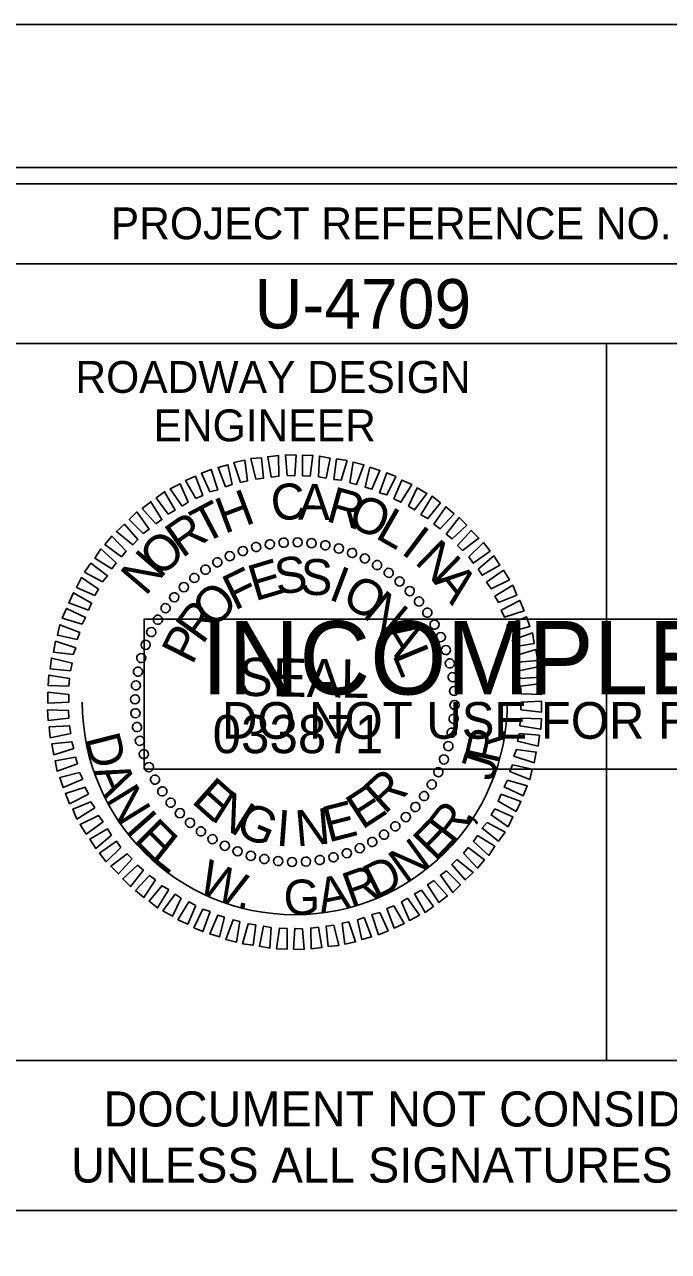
# Model space of a CAD drawing. Extents: x 1779926 to 1781626, y 618464 to 619564.
# Drawn here: x 1781401.6 to 1781502.7, y 619371.7 to 619564.2 of the extents above; entities that cross this region are included whole.
import ezdxf

# ---------------------------------------------------------------- set-up
doc = ezdxf.new("R2010")
doc.units = 0
for name, color, linetype in [('Old_Level_58', 7, 'Continuous'), ('Scratch_Level_0', 7, 'Continuous'), ('Sheet Data Field CELL', 7, 'Continuous'), ('Sheet Plot Border Inside CELL', 7, 'Continuous'), ('Sheet Plot Border Outside CELL', 7, 'Continuous'), ('Sheet Professional Seal CELL', 7, 'Continuous'), ('Sheet Profile CELL', 7, 'Continuous'), ('Sheet Profile Grid Major CELL', 7, 'Continuous'), ('Sheet Profile Grid Minor CELL', 7, 'Continuous'), ('Sheet Sticker Exception Certification CELL', 7, 'Continuous'), ('Sheet Sticker Incomplete CELL', 7, 'Continuous')]:
    doc.layers.add(name, color=color, linetype=linetype)

msp = doc.modelspace()

# ---------------------------------------------------------------- linework, layer by layer
at = {"layer": 'Old_Level_58'}
msp.add_lwpolyline([(1781392.96, 619378.14), (1781592.95, 619378.14), (1781592.95, 619314.19), (1781392.96, 619314.19)], close=True, dxfattribs=at)
at = {"layer": 'Scratch_Level_0'}
msp.add_arc((1781444.02, 619457.88), 33.36, 180, 360, dxfattribs=at)
at = {"layer": 'Sheet Plot Border Inside CELL'}
msp.add_lwpolyline([(1779938.96, 618486.64), (1781605.46, 618486.64), (1781605.46, 619541.74), (1779938.96, 619541.74)], close=True, dxfattribs=at)
at = {"layer": 'Sheet Plot Border Outside CELL'}
msp.add_lwpolyline([(1779925.96, 618464.19), (1781625.96, 618464.19), (1781625.96, 619564.19), (1779925.96, 619564.19)], close=True, dxfattribs=at)
at = {"layer": 'Sheet Professional Seal CELL'}
for p, q in [((1781440.12, 619482.63), (1781440.12, 619482.63)), ((1781442.27, 619482.93), (1781442.27, 619482.93)), ((1781444.47, 619482.98), (1781444.47, 619482.98)), ((1781446.67, 619482.83), (1781446.67, 619482.83)), ((1781448.82, 619482.48), (1781448.82, 619482.48)), ((1781433.82, 619480.83), (1781433.82, 619480.83)), ((1781435.82, 619481.63), (1781435.82, 619481.63)), ((1781437.92, 619482.23), (1781437.92, 619482.23)), ((1781450.92, 619482.03), (1781450.92, 619482.03)), ((1781453.02, 619481.33), (1781453.02, 619481.33)), ((1781455.02, 619480.43), (1781455.02, 619480.43)), ((1781429.97, 619478.68), (1781429.97, 619478.68)), ((1781431.87, 619479.83), (1781431.87, 619479.83)), ((1781456.97, 619479.43), (1781456.97, 619479.43)), ((1781428.22, 619477.43), (1781428.22, 619477.43)), ((1781458.77, 619478.18), (1781458.77, 619478.18)), ((1781460.52, 619476.83), (1781460.52, 619476.83)), ((1781426.57, 619475.93), (1781426.57, 619475.93)), ((1781462.07, 619475.33), (1781462.07, 619475.33)), ((1781425.07, 619474.38), (1781425.07, 619474.38)), ((1781463.57, 619473.68), (1781463.57, 619473.68)), ((1781422.47, 619470.83), (1781422.47, 619470.83)), ((1781423.72, 619472.63), (1781423.72, 619472.63)), ((1781464.82, 619471.93), (1781464.82, 619471.93)), ((1781421.47, 619468.88), (1781421.47, 619468.88)), ((1781465.97, 619470.03), (1781465.97, 619470.03)), ((1781466.97, 619468.08), (1781466.97, 619468.08)), ((1781420.57, 619466.88), (1781420.57, 619466.88)), ((1781467.77, 619466.08), (1781467.77, 619466.08)), ((1781419.87, 619464.78), (1781419.87, 619464.78)), ((1781468.37, 619463.98), (1781468.37, 619463.98)), ((1781419.42, 619462.68), (1781419.42, 619462.68)), ((1781468.77, 619461.78), (1781468.77, 619461.78)), ((1781419.07, 619460.53), (1781419.07, 619460.53)), ((1781469.07, 619459.63), (1781469.07, 619459.63)), ((1781418.92, 619458.33), (1781418.92, 619458.33)), ((1781444.02, 619457.88), (1781444.02, 619457.88)), ((1781469.12, 619457.43), (1781469.12, 619457.43)), ((1781418.97, 619456.13), (1781418.97, 619456.13)), ((1781419.27, 619453.98), (1781419.27, 619453.98)), ((1781468.97, 619455.23), (1781468.97, 619455.23)), ((1781419.67, 619451.78), (1781419.67, 619451.78)), ((1781468.62, 619453.08), (1781468.62, 619453.08)), ((1781420.27, 619449.68), (1781420.27, 619449.68)), ((1781468.17, 619450.98), (1781468.17, 619450.98)), ((1781421.07, 619447.68), (1781421.07, 619447.68)), ((1781467.47, 619448.88), (1781467.47, 619448.88)), ((1781466.57, 619446.88), (1781466.57, 619446.88)), ((1781422.07, 619445.73), (1781422.07, 619445.73)), ((1781423.22, 619443.83), (1781423.22, 619443.83)), ((1781465.57, 619444.93), (1781465.57, 619444.93)), ((1781424.47, 619442.08), (1781424.47, 619442.08)), ((1781464.32, 619443.13), (1781464.32, 619443.13)), ((1781425.97, 619440.43), (1781425.97, 619440.43)), ((1781462.97, 619441.38), (1781462.97, 619441.38)), ((1781427.52, 619438.93), (1781427.52, 619438.93)), ((1781459.82, 619438.33), (1781459.82, 619438.33)), ((1781461.47, 619439.83), (1781461.47, 619439.83)), ((1781429.27, 619437.58), (1781429.27, 619437.58)), ((1781431.07, 619436.33), (1781431.07, 619436.33)), ((1781458.07, 619437.08), (1781458.07, 619437.08)), ((1781433.02, 619435.33), (1781433.02, 619435.33)), ((1781435.02, 619434.43), (1781435.02, 619434.43)), ((1781454.22, 619434.93), (1781454.22, 619434.93)), ((1781456.17, 619435.93), (1781456.17, 619435.93)), ((1781437.12, 619433.73), (1781437.12, 619433.73)), ((1781439.22, 619433.28), (1781439.22, 619433.28)), ((1781441.37, 619432.93), (1781441.37, 619432.93)), ((1781443.57, 619432.78), (1781443.57, 619432.78)), ((1781445.77, 619432.83), (1781445.77, 619432.83)), ((1781447.92, 619433.13), (1781447.92, 619433.13)), ((1781450.12, 619433.53), (1781450.12, 619433.53)), ((1781452.22, 619434.13), (1781452.22, 619434.13))]:
    msp.add_line(p, q, dxfattribs=at)
for points in [[(1781435.52, 619492.33), (1781434.47, 619495.48), (1781436.17, 619495.83), (1781436.57, 619492.58)], [(1781437.92, 619492.88), (1781437.12, 619496.08), (1781438.77, 619496.23), (1781439.12, 619493.03)], [(1781440.32, 619493.18), (1781439.77, 619496.38), (1781441.47, 619496.58), (1781441.52, 619493.33)], [(1781442.82, 619493.43), (1781442.57, 619496.68), (1781444.22, 619496.63), (1781444.02, 619493.38)], [(1781445.22, 619493.38), (1781445.22, 619496.63), (1781446.87, 619496.58), (1781446.42, 619493.33)], [(1781447.72, 619493.23), (1781447.92, 619496.48), (1781449.57, 619496.18), (1781448.92, 619493.03)], [(1781450.12, 619492.83), (1781450.57, 619496.03), (1781452.22, 619495.78), (1781451.32, 619492.68)], [(1781430.67, 619490.88), (1781429.37, 619493.78), (1781430.87, 619494.38), (1781431.92, 619491.18)], [(1781433.12, 619491.68), (1781431.97, 619494.68), (1781433.52, 619495.13), (1781434.17, 619492.03)], [(1781452.67, 619492.28), (1781453.17, 619495.53), (1781454.87, 619495.13), (1781453.72, 619492.03)], [(1781455.07, 619491.63), (1781455.82, 619494.73), (1781457.37, 619494.23), (1781456.12, 619491.28)], [(1781457.32, 619490.73), (1781458.47, 619493.88), (1781459.87, 619493.28), (1781458.47, 619490.38)], [(1781426.32, 619488.63), (1781424.47, 619491.33), (1781426.02, 619492.13), (1781427.27, 619489.23)], [(1781428.47, 619489.83), (1781426.87, 619492.63), (1781428.42, 619493.33), (1781429.57, 619490.28)], [(1781459.57, 619489.78), (1781460.82, 619492.73), (1781462.37, 619492.03), (1781460.67, 619489.23)], [(1781424.12, 619487.38), (1781422.27, 619489.93), (1781423.57, 619490.88), (1781425.22, 619487.98)], [(1781461.87, 619488.63), (1781463.22, 619491.48), (1781464.72, 619490.63), (1781462.82, 619488.03)], [(1781463.82, 619487.28), (1781465.57, 619490.18), (1781466.87, 619489.13), (1781464.92, 619486.68)], [(1781422.22, 619485.88), (1781420.07, 619488.28), (1781421.42, 619489.33), (1781423.17, 619486.53)], [(1781465.87, 619485.78), (1781467.72, 619488.53), (1781469.02, 619487.43), (1781466.82, 619485.08)], [(1781420.22, 619484.33), (1781418.02, 619486.53), (1781419.22, 619487.73), (1781421.17, 619485.03)], [(1781467.77, 619484.23), (1781469.82, 619486.83), (1781471.02, 619485.63), (1781468.72, 619483.48)], [(1781418.57, 619482.58), (1781416.02, 619484.63), (1781417.27, 619485.78), (1781419.37, 619483.38)], [(1781469.57, 619482.48), (1781471.72, 619484.83), (1781472.92, 619483.63), (1781470.32, 619481.68)], [(1781416.82, 619480.68), (1781414.22, 619482.63), (1781415.32, 619483.93), (1781417.52, 619481.58)], [(1781471.32, 619480.68), (1781473.62, 619482.93), (1781474.67, 619481.58), (1781472.02, 619479.68)], [(1781415.32, 619478.78), (1781412.62, 619480.48), (1781413.57, 619481.93), (1781415.97, 619479.73)], [(1781472.82, 619478.73), (1781475.27, 619480.83), (1781476.22, 619479.38), (1781473.42, 619477.78)], [(1781413.82, 619476.78), (1781411.02, 619478.28), (1781412.02, 619479.68), (1781414.62, 619477.68)], [(1781474.12, 619476.68), (1781476.77, 619478.58), (1781477.72, 619477.08), (1781474.82, 619475.68)], [(1781412.62, 619474.63), (1781409.77, 619475.88), (1781410.52, 619477.43), (1781413.22, 619475.58)], [(1781411.62, 619472.33), (1781408.52, 619473.48), (1781409.27, 619475.03), (1781412.12, 619473.43)], [(1781475.42, 619474.48), (1781478.22, 619476.23), (1781478.87, 619474.68), (1781476.02, 619473.53)], [(1781476.42, 619472.33), (1781479.37, 619473.83), (1781480.02, 619472.23), (1781476.92, 619471.23)], [(1781410.62, 619470.13), (1781407.52, 619471.03), (1781408.17, 619472.58), (1781411.17, 619471.18)], [(1781477.32, 619469.98), (1781480.37, 619471.28), (1781480.92, 619469.73), (1781477.82, 619468.93)], [(1781409.87, 619467.73), (1781406.77, 619468.38), (1781407.12, 619470.03), (1781410.27, 619468.78)], [(1781409.22, 619465.33), (1781406.12, 619465.73), (1781406.47, 619467.43), (1781409.62, 619466.38)], [(1781478.12, 619467.58), (1781481.32, 619468.73), (1781481.62, 619467.08), (1781478.47, 619466.53)], [(1781478.72, 619465.18), (1781481.87, 619466.13), (1781482.17, 619464.43), (1781479.02, 619464.13)], [(1781408.82, 619462.78), (1781405.62, 619463.08), (1781405.82, 619464.78), (1781409.07, 619463.98)], [(1781479.17, 619462.78), (1781482.42, 619463.48), (1781482.57, 619461.78), (1781479.37, 619461.58)], [(1781408.57, 619460.38), (1781405.32, 619460.48), (1781405.42, 619462.13), (1781408.67, 619461.58)], [(1781408.52, 619457.88), (1781405.27, 619457.73), (1781405.27, 619459.43), (1781408.52, 619459.08)], [(1781479.47, 619460.38), (1781482.72, 619460.78), (1781482.82, 619459.08), (1781479.57, 619459.18)], [(1781479.52, 619457.88), (1781482.77, 619458.03), (1781482.77, 619456.33), (1781479.52, 619456.68)], [(1781408.57, 619455.38), (1781405.32, 619454.98), (1781405.22, 619456.68), (1781408.47, 619456.58)], [(1781479.47, 619455.38), (1781482.72, 619455.28), (1781482.62, 619453.63), (1781479.37, 619454.18)], [(1781408.87, 619452.98), (1781405.62, 619452.28), (1781405.47, 619453.98), (1781408.67, 619454.18)], [(1781409.32, 619450.58), (1781406.17, 619449.63), (1781405.87, 619451.33), (1781409.02, 619451.63)], [(1781479.22, 619452.98), (1781482.42, 619452.68), (1781482.22, 619450.98), (1781478.97, 619451.78)], [(1781478.82, 619450.43), (1781481.92, 619450.03), (1781481.57, 619448.33), (1781478.42, 619449.38)], [(1781409.92, 619448.18), (1781406.72, 619447.03), (1781406.42, 619448.68), (1781409.57, 619449.23)], [(1781478.17, 619448.03), (1781481.27, 619447.38), (1781480.92, 619445.73), (1781477.77, 619446.98)], [(1781410.72, 619445.78), (1781407.67, 619444.48), (1781407.12, 619446.03), (1781410.22, 619446.83)], [(1781411.62, 619443.43), (1781408.67, 619441.93), (1781408.02, 619443.53), (1781411.12, 619444.53)], [(1781477.42, 619445.63), (1781480.52, 619444.73), (1781479.87, 619443.18), (1781476.87, 619444.58)], [(1781412.62, 619441.28), (1781409.82, 619439.53), (1781409.17, 619441.08), (1781412.02, 619442.23)], [(1781476.42, 619443.43), (1781479.52, 619442.28), (1781478.77, 619440.73), (1781475.92, 619442.33)], [(1781413.92, 619439.08), (1781411.27, 619437.18), (1781410.32, 619438.68), (1781413.22, 619440.08)], [(1781475.42, 619441.13), (1781478.27, 619439.88), (1781477.52, 619438.33), (1781474.82, 619440.18)], [(1781474.22, 619438.98), (1781477.02, 619437.48), (1781476.02, 619436.08), (1781473.42, 619438.08)], [(1781415.22, 619437.03), (1781412.77, 619434.93), (1781411.82, 619436.38), (1781414.62, 619437.98)], [(1781472.72, 619436.98), (1781475.42, 619435.28), (1781474.47, 619433.83), (1781472.07, 619436.03)], [(1781416.72, 619435.08), (1781414.42, 619432.83), (1781413.37, 619434.18), (1781416.02, 619436.08)], [(1781471.22, 619435.08), (1781473.82, 619433.13), (1781472.72, 619431.83), (1781470.52, 619434.18)], [(1781418.47, 619433.28), (1781416.32, 619430.93), (1781415.12, 619432.13), (1781417.72, 619434.08)], [(1781420.27, 619431.53), (1781418.22, 619428.93), (1781417.02, 619430.13), (1781419.32, 619432.28)], [(1781469.47, 619433.18), (1781472.02, 619431.13), (1781470.77, 619429.98), (1781468.67, 619432.38)], [(1781422.17, 619429.98), (1781420.32, 619427.23), (1781419.02, 619428.33), (1781421.22, 619430.68)], [(1781467.82, 619431.43), (1781470.02, 619429.23), (1781468.82, 619428.03), (1781466.87, 619430.73)], [(1781424.22, 619428.48), (1781422.47, 619425.58), (1781421.17, 619426.63), (1781423.12, 619429.08)], [(1781465.82, 619429.88), (1781467.97, 619427.48), (1781466.62, 619426.43), (1781464.87, 619429.23)], [(1781426.17, 619427.13), (1781424.82, 619424.28), (1781423.32, 619425.13), (1781425.22, 619427.73)], [(1781428.47, 619425.98), (1781427.22, 619423.03), (1781425.67, 619423.73), (1781427.37, 619426.53)], [(1781461.72, 619427.13), (1781463.57, 619424.43), (1781462.02, 619423.63), (1781460.77, 619426.53)], [(1781463.92, 619428.38), (1781465.77, 619425.83), (1781464.47, 619424.88), (1781462.82, 619427.78)], [(1781430.72, 619425.03), (1781429.57, 619421.88), (1781428.17, 619422.48), (1781429.57, 619425.38)], [(1781457.37, 619424.88), (1781458.67, 619421.98), (1781457.17, 619421.38), (1781456.12, 619424.58)], [(1781459.57, 619425.93), (1781461.17, 619423.13), (1781459.62, 619422.43), (1781458.47, 619425.48)], [(1781432.97, 619424.13), (1781432.22, 619421.03), (1781430.67, 619421.53), (1781431.92, 619424.48)], [(1781435.37, 619423.48), (1781434.87, 619420.23), (1781433.17, 619420.63), (1781434.32, 619423.73)], [(1781437.92, 619422.93), (1781437.47, 619419.73), (1781435.82, 619419.98), (1781436.72, 619423.08)], [(1781440.32, 619422.53), (1781440.12, 619419.28), (1781438.47, 619419.58), (1781439.12, 619422.73)], [(1781450.12, 619422.88), (1781450.92, 619419.68), (1781449.27, 619419.53), (1781448.92, 619422.73)], [(1781452.52, 619423.43), (1781453.57, 619420.28), (1781451.87, 619419.93), (1781451.47, 619423.18)], [(1781454.92, 619424.08), (1781456.07, 619421.08), (1781454.52, 619420.63), (1781453.87, 619423.73)], [(1781442.82, 619422.38), (1781442.82, 619419.13), (1781441.17, 619419.18), (1781441.62, 619422.43)], [(1781445.22, 619422.33), (1781445.47, 619419.08), (1781443.82, 619419.13), (1781444.02, 619422.38)], [(1781447.72, 619422.58), (1781448.27, 619419.38), (1781446.57, 619419.18), (1781446.52, 619422.43)]]:
    msp.add_lwpolyline(points, close=True, dxfattribs=at)
for centre, major_axis in [((1781435.86, 619481.59), (-0.234, 0.681)), ((1781437.95, 619482.22), (-0.174, 0.699)), ((1781440.1, 619482.65), (-0.113, 0.711)), ((1781442.27, 619482.9), (-0.05, 0.718)), ((1781444.46, 619482.96), (0.013, 0.72)), ((1781446.64, 619482.82), (0.075, 0.716)), ((1781448.81, 619482.5), (0.137, 0.707)), ((1781450.93, 619481.99), (0.198, 0.692)), ((1781431.86, 619479.82), (-0.349, 0.63)), ((1781433.82, 619480.79), (-0.293, 0.658)), ((1781453.01, 619481.29), (0.258, 0.672)), ((1781455.01, 619480.42), (0.316, 0.647)), ((1781430, 619478.67), (-0.403, 0.597)), ((1781456.94, 619479.38), (0.371, 0.617)), ((1781458.76, 619478.17), (0.423, 0.582)), ((1781426.6, 619475.92), (-0.5, 0.518)), ((1781428.24, 619477.37), (-0.453, 0.56)), ((1781460.47, 619476.81), (0.472, 0.543)), ((1781425.09, 619474.33), (-0.543, 0.472)), ((1781462.06, 619475.3), (0.518, 0.5)), ((1781423.73, 619472.62), (-0.582, 0.423)), ((1781463.51, 619473.66), (0.56, 0.453)), ((1781464.81, 619471.9), (0.597, 0.403)), ((1781422.52, 619470.8), (-0.617, 0.371)), ((1781465.96, 619470.04), (0.63, 0.349)), ((1781421.48, 619468.87), (-0.647, 0.316)), ((1781466.93, 619468.08), (0.658, 0.293)), ((1781420.61, 619466.87), (-0.672, 0.258)), ((1781419.91, 619464.79), (-0.692, 0.198)), ((1781467.73, 619466.05), (0.681, 0.234)), ((1781419.4, 619462.67), (-0.707, 0.137)), ((1781468.36, 619463.95), (0.699, 0.174)), ((1781419.08, 619460.5), (-0.716, 0.075)), ((1781468.79, 619461.8), (0.711, 0.113)), ((1781469.04, 619459.63), (0.718, 0.05)), ((1781418.94, 619458.32), (-0.72, 0.013)), ((1781469.1, 619457.44), (0.72, -0.013)), ((1781419, 619456.13), (-0.718, -0.05)), ((1781468.96, 619455.26), (0.716, -0.075)), ((1781419.25, 619453.96), (-0.711, -0.113)), ((1781468.64, 619453.09), (0.707, -0.137)), ((1781419.69, 619451.81), (-0.699, -0.174)), ((1781468.13, 619450.97), (0.692, -0.198)), ((1781420.31, 619449.71), (-0.681, -0.234)), ((1781467.43, 619448.89), (0.672, -0.258)), ((1781421.11, 619447.68), (-0.658, -0.293)), ((1781466.56, 619446.89), (0.647, -0.316)), ((1781422.08, 619445.72), (-0.63, -0.349)), ((1781465.52, 619444.96), (0.617, -0.371)), ((1781423.23, 619443.86), (-0.597, -0.403)), ((1781464.31, 619443.14), (0.582, -0.423)), ((1781424.53, 619442.1), (-0.56, -0.453)), ((1781462.95, 619441.43), (0.543, -0.472)), ((1781425.98, 619440.46), (-0.518, -0.5)), ((1781461.44, 619439.84), (0.5, -0.518)), ((1781427.57, 619438.95), (-0.472, -0.543)), ((1781429.28, 619437.59), (-0.423, -0.582)), ((1781459.8, 619438.39), (0.453, -0.56)), ((1781431.1, 619436.38), (-0.371, -0.617)), ((1781433.03, 619435.34), (-0.316, -0.647)), ((1781456.18, 619435.94), (0.349, -0.63)), ((1781458.04, 619437.09), (0.403, -0.597)), ((1781435.03, 619434.47), (-0.258, -0.672)), ((1781437.11, 619433.77), (-0.198, -0.692)), ((1781450.09, 619433.54), (0.174, -0.699)), ((1781452.19, 619434.17), (0.234, -0.681)), ((1781454.22, 619434.97), (0.293, -0.658)), ((1781439.23, 619433.26), (-0.137, -0.707)), ((1781441.4, 619432.94), (-0.075, -0.716)), ((1781443.58, 619432.8), (-0.013, -0.72)), ((1781445.77, 619432.86), (0.05, -0.718)), ((1781447.94, 619433.11), (0.113, -0.711))]:
    msp.add_ellipse(centre, major_axis=major_axis, ratio=0.999708, dxfattribs=at)
at = {"layer": 'Sheet Profile CELL'}
for p, q in [((1781392.91, 619526.64), (1781592.96, 619526.64)), ((1781492.96, 619514.14), (1781492.96, 619401.69))]:
    msp.add_line(p, q, dxfattribs=at)
for points in [[(1781592.96, 619539.19), (1780092.96, 619539.19), (1780092.96, 618489.19), (1781592.96, 618489.19)], [(1781392.91, 619539.19), (1781592.96, 619539.19), (1781592.96, 619514.14), (1781392.91, 619514.14)], [(1781392.91, 619514.14), (1781492.96, 619514.14), (1781492.96, 619401.64), (1781392.91, 619401.64)], [(1781492.96, 619514.14), (1781592.96, 619514.14), (1781592.96, 619401.64), (1781492.96, 619401.64)]]:
    msp.add_lwpolyline(points, close=True, dxfattribs=at)
at = {"layer": 'Sheet Profile Grid Major CELL'}
msp.add_lwpolyline([(1780842.96, 619039.19), (1780892.96, 619039.19), (1780892.96, 619539.19), (1780942.96, 619539.19), (1780942.96, 619039.19), (1780992.96, 619039.19), (1780992.96, 619539.19), (1781042.96, 619539.19), (1781042.96, 619039.19), (1781092.96, 619039.19), (1781092.96, 619539.19), (1781142.96, 619539.19), (1781142.96, 619039.19), (1781192.96, 619039.19), (1781192.96, 619539.19), (1781242.96, 619539.19), (1781242.96, 619039.19), (1781292.96, 619039.19), (1781292.96, 619539.19), (1781342.96, 619539.19), (1781342.96, 619039.19), (1781392.96, 619039.19), (1781392.96, 619539.19), (1781419.26, 619539.19)], dxfattribs=at)
at = {"layer": 'Sheet Sticker Exception Certification CELL'}
for p, q in [((1781392.91, 619401.64), (1781592.95, 619401.64)), ((1781392.91, 619401.64), (1781592.95, 619401.64)), ((1781592.95, 619378.14), (1781392.91, 619378.14)), ((1781592.95, 619378.14), (1781392.91, 619378.14))]:
    msp.add_line(p, q, dxfattribs=at)
at = {"layer": 'Sheet Sticker Incomplete CELL'}
msp.add_lwpolyline([(1781420.37, 619447.38), (1781420.37, 619470.88), (1781567.37, 619470.88), (1781567.37, 619447.38)], close=True, dxfattribs=at)

# ---------------------------------------------------------------- texts
at = {"layer": 'Sheet Data Field CELL'}
msp.add_text('U-4709', height=7.75, dxfattribs=at).set_placement((1781437.72, 619516.5))
at = {"layer": 'Sheet Professional Seal CELL'}
for s, height, rotation, p in [('C', 5.64, 6.2199, (1781440.57, 619486.23)), ('A', 5.64, 359.0203, (1781444.52, 619486.53)), ('H', 5.64, 20.6195, (1781432.97, 619484.23)), ('R', 5.64, 344.6211, (1781448.72, 619486.33)), ('O', 5.64, 337.4212, (1781452.07, 619485.58)), ('T', 5.64, 27.8198, (1781429.72, 619482.58)), ('L', 5.64, 330.2209, (1781456.47, 619483.73)), ('R', 5.64, 35.0205, (1781426.32, 619480.38)), ('O', 5.64, 42.2217, (1781422.87, 619477.28)), ('I', 5.64, 323.0201, (1781460.52, 619481.33)), ('N', 5.64, 315.8189, (1781462.67, 619479.78)), ('N', 5.64, 49.4235, (1781420.57, 619474.38)), ('S', 5.64, 7.2556, (1781441.22, 619474.73)), ('S', 5.64, 357.9004, (1781444.82, 619474.78)), ('F', 5.64, 25.967, (1781434.57, 619472.18)), ('E', 5.64, 16.6111, (1781437.77, 619473.68)), ('I', 5.64, 339.1896, (1781449.12, 619474.08)), ('A', 5.64, 308.6172, (1781465.62, 619476.83)), ('O', 5.64, 329.8335, (1781451.12, 619473.38)), ('O', 5.64, 44.6812, (1781431.27, 619469.23)), ('N', 5.64, 320.4766, (1781454.47, 619471.38)), ('R', 5.64, 54.0397, (1781429.52, 619466.78)), ('P', 5.64, 63.3989, (1781427.92, 619463.58)), ('A', 5.64, 301.7603, (1781457.32, 619468.78)), ('L', 5.64, 292.4008, (1781459.27, 619465.33)), ('SEAL', 5.998, 359, (1781435.17, 619458.88)), ('E', 5.64, 318.2769, (1781427.62, 619442.23)), ('R', 5.64, 42.4814, (1781458.12, 619440.13)), ('N', 5.64, 327.634, (1781430.62, 619439.53)), ('E', 5.64, 33.1241, (1781454.57, 619437.78)), ('E', 5.64, 14.4118, (1781449.27, 619435.83)), ('G', 5.64, 336.9902, (1781434.42, 619437.28)), ('I', 5.64, 355.7012, (1781440.97, 619435.38)), ('N', 5.64, 5.0564, (1781444.32, 619435.23))]:
    msp.add_text(s, height=height, rotation=rotation, dxfattribs=at).set_placement(p)
at = {"layer": 'Sheet Profile CELL'}
for s, height, p in [('PROJECT REFERENCE NO.', 5.0001, (1781415.12, 619530.5)), ('ROADWAY DESIGN', 5.0001, (1781409.57, 619506.4)), ('ENGINEER', 5, (1781421.82, 619498.8))]:
    msp.add_text(s, height=height, dxfattribs=at).set_placement(p)
at = {"layer": 'Sheet Profile Grid Minor CELL'}
msp.add_text('033871', height=5.998, dxfattribs=at).set_placement((1781431.12, 619449.87))
for s, rotation, p in [('R', 77.3541, (1781475.99, 619447.98)), ('D', 284.2682, (1781411.03, 619452.24)), ('.', 84.2805, (1781476.95, 619451.91)), ('J', 72.4855, (1781475.04, 619445.3)), ('A', 293.4128, (1781412.35, 619447.07)), ('N', 301.5986, (1781414.21, 619442.67)), ('R', 52.3788, (1781468.82, 619435.4)), ('I', 311.5304, (1781417.28, 619437.75)), (',', 59.3052, (1781471.35, 619438.56)), ('E', 315.0508, (1781418.57, 619436.15)), ('E', 45.7958, (1781466.08, 619432.71)), ('L', 321.6338, (1781421.22, 619433.37)), ('N', 35.8641, (1781461.41, 619429.28)), ('W', 336.8891, (1781428.48, 619428.24)), ('D', 26.7195, (1781456.64, 619426.88)), ('A', 11.6072, (1781448.13, 619424.66)), ('R', 19.793, (1781452.81, 619425.59)), ('G', 1.6755, (1781442.33, 619424.45)), ('.', 348.4952, (1781434.76, 619425.72))]:
    msp.add_text(s, height=5.5, rotation=rotation, dxfattribs=at).set_placement(p)
at = {"layer": 'Sheet Sticker Exception Certification CELL'}
for s, p in [('DOCUMENT NOT CONSIDERED FINAL', (1781413.98, 619391.3)), ('DOCUMENT NOT CONSIDERED FINAL', (1781413.98, 619391.3)), ('UNLESS ALL SIGNATURES COMPLETED', (1781408.91, 619382.5)), ('UNLESS ALL SIGNATURES COMPLETED', (1781408.91, 619382.5))]:
    msp.add_text(s, height=5.5, dxfattribs=at).set_placement(p)
at = {"layer": 'Sheet Sticker Incomplete CELL'}
for s, height, p in [('INCOMPLETE PLANS', 11.52, (1781429.32, 619459.08)), ('DO NOT USE FOR R/W ACQUISITION', 5.76, (1781432.57, 619452.13))]:
    msp.add_text(s, height=height, dxfattribs=at).set_placement(p)

doc.saveas('drawing.dxf')
